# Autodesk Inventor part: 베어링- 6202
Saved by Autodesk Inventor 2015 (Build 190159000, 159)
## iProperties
Created: 2025-08
Part Number: 베어링- 6202
Material: 일반
Document SubType Name: Modeling
Designer: USER
Density: 1 g/cm^3
Appearance: 기본값
Author: USER
Author: jhkim
Description: 깊은 그루브 볼 베어링
Creation Date: 2025-08-05
Sending System: Autodesk Inventor 2026
Preprocessor: ST-DEVELOPER v20.1
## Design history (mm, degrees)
node "베어링- 62021"
body "Solid1"
node "Solid1_1"
node "Solid1_2"
node "Solid1_3"
node "Solid1_4"
node "Solid1_5"
node "Solid1_6"
node "Solid1_7"
node "Solid1_8"
node "Solid1_9"
node "기준1"
node "기준2"
node "기준3"
node "기준4"
node "기준5"
node "기준6"
node "기준7"
node "기준8"
node "기준9"
node "기준10"
